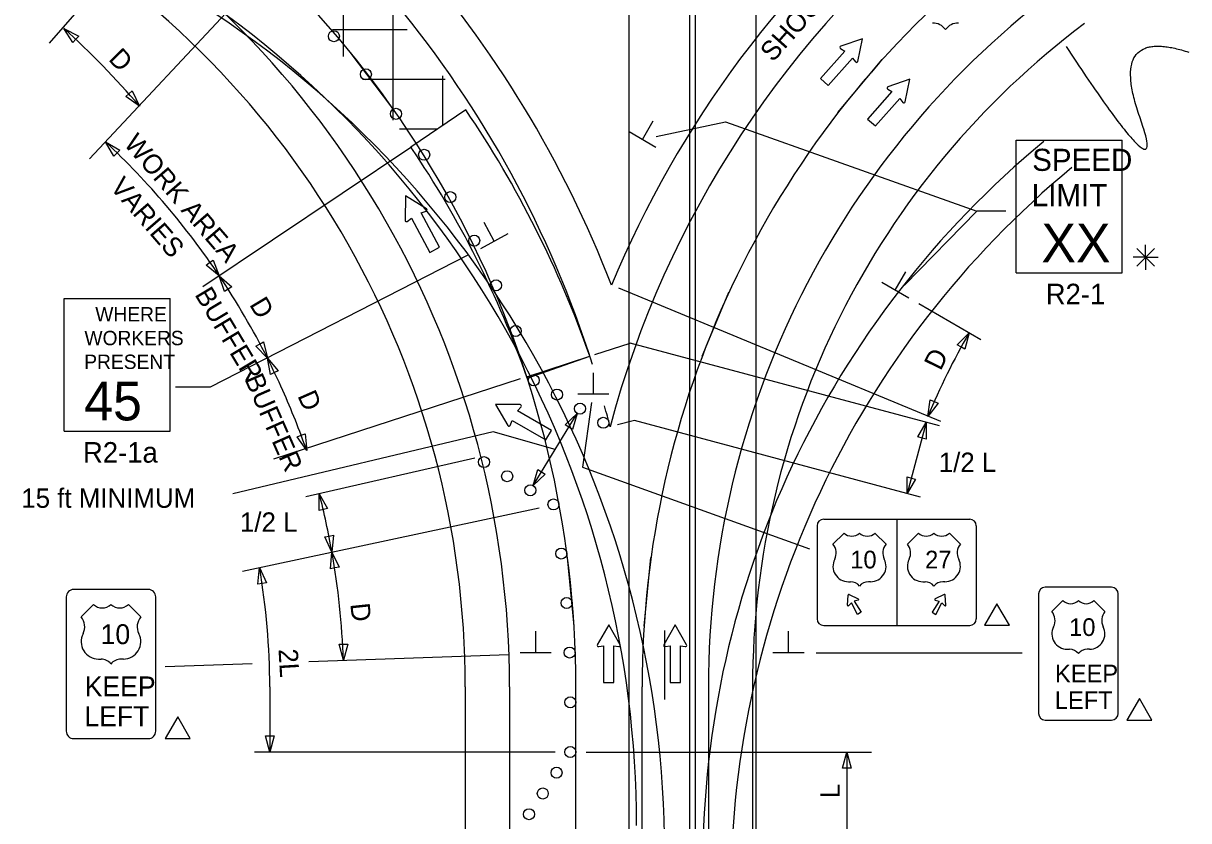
# Model space of a CAD drawing. Extents: x 16284 to 18465, y 5417 to 6974.
# Drawn here: x 16725.1 to 17147, y 6516.3 to 6805 of the extents above; entities that cross this region are included whole.
import ezdxf

# ---------------------------------------------------------------- set-up
doc = ezdxf.new("R2010")
doc.units = 0
for name, color, linetype in [('ALI_LEGAL_EX', 7, 'Continuous'), ('Level 3', 7, 'Continuous'), ('MT_SCRATCH_LEVEL_A', 7, 'Continuous'), ('MT_SCRATCH_LEVEL_E', 7, 'Continuous'), ('PAVT_EDGE_EX', 7, 'Continuous'), ('TRAFFIC_SIGNS_PR', 7, 'Continuous'), ('TYPICAL_EX', 7, 'Continuous'), ('TYPICAL_TEXT_DIMEN_PR', 7, 'Continuous')]:
    doc.layers.add(name, color=color, linetype=linetype)

msp = doc.modelspace()

# ---------------------------------------------------------------- linework, layer by layer
at = {"layer": 'ALI_LEGAL_EX'}
for p, q in [((16944.3, 6974.12), (16944.3, 6155.98)), ((16968.3, 6974.12), (16968.3, 6155.98)), ((16966.29, 6836.53), (16966.29, 5997.6)), ((16990.29, 6836.53), (16990.29, 5997.6)), ((16925.13, 6287.02), (16925.13, 6564.7)), ((16949.13, 6287.02), (16949.13, 6564.7))]:
    msp.add_line(p, q, dxfattribs=at)
for points in [[(16858.51, 6774.55), (16843.42, 6794.48)], [(17020.02, 6772.64), (17036.07, 6791.8)], [(16970.92, 6684.51), (16980.56, 6707.58)], [(16924.57, 6586.71), (16922.17, 6611.6)], [(16949.84, 6586.69), (16952.34, 6611.56)], [(16957.27, 6585.13), (16957.27, 6560.13)]]:
    msp.add_lwpolyline(points, dxfattribs=at)
for centre, radius, start, end in [((16561.13, 6564.7), 364, 0, 53.7921), ((17289.13, 6564.7), 340, 129.5666, 180), ((16583.12, 6514.52), 364, 0, 57.2958), ((16593.27, 6505.1), 364, 0, 57.2958), ((17311.12, 6500.03), 340, 129.5666, 180), ((17321.27, 6490.61), 340, 129.5666, 180)]:
    msp.add_arc(centre, radius, start, end, dxfattribs=at)
at = {"layer": 'Level 3'}
for p, q in [((16954.27, 6763.95), (16979.34, 6769.32)), ((16979.34, 6769.32), (17070.39, 6737)), ((17070.39, 6737), (17044.11, 6710.12)), ((17080.82, 6737), (17070.39, 6737))]:
    msp.add_line(p, q, dxfattribs=at)
at = {"layer": 'MT_SCRATCH_LEVEL_A'}
for p, q in [((16840.96, 6792.95), (16840.96, 6828.84)), ((16858.96, 6769.95), (16858.96, 6808.85)), ((16837.08, 6802.72), (16864.07, 6802.72)), ((16876.96, 6767.98), (16876.96, 6785.97)), ((16847.88, 6784.72), (16877.88, 6784.72)), ((16861.34, 6766.72), (16875.11, 6766.72)), ((16907.37, 6677.02), (16930.2, 6684.43))]:
    msp.add_line(p, q, dxfattribs=at)
at = {"layer": 'MT_SCRATCH_LEVEL_E'}
for p, q in [((17028.96, 6799.34), (17021.08, 6796.66)), ((17027.25, 6791.17), (17028.96, 6799.34)), ((17022.52, 6794.88), (17013.72, 6784.97)), ((17020.99, 6795.82), (17022.52, 6794.88)), ((17016.51, 6782.48), (17025.32, 6792.39)), ((17025.32, 6792.39), (17026.44, 6790.98)), ((17013.72, 6784.97), (17016.51, 6782.48)), ((17038.07, 6781.17), (17039.61, 6780.22)), ((17046.05, 6784.68), (17038.16, 6782)), ((17044.34, 6776.51), (17046.05, 6784.68)), ((17039.61, 6780.22), (17030.8, 6770.31)), ((17033.6, 6767.83), (17042.4, 6777.74)), ((17042.4, 6777.74), (17043.52, 6776.32)), ((17030.8, 6770.31), (17033.6, 6767.83)), ((16937.03, 6587.21), (16932.92, 6579.97)), ((16941.18, 6579.97), (16937.03, 6587.21)), ((16961.09, 6587.21), (16956.98, 6579.97)), ((16965.24, 6579.97), (16961.09, 6587.21)), ((16933.41, 6579.29), (16935.18, 6579.6)), ((16935.18, 6579.6), (16935.18, 6566.35)), ((16938.92, 6566.35), (16938.92, 6579.6)), ((16938.92, 6579.6), (16940.7, 6579.29)), ((16957.46, 6579.29), (16959.24, 6579.6)), ((16959.24, 6579.6), (16959.24, 6566.35)), ((16962.98, 6566.35), (16962.98, 6579.6)), ((16962.98, 6579.6), (16964.76, 6579.29)), ((16935.18, 6566.35), (16938.92, 6566.35)), ((16959.24, 6566.35), (16962.98, 6566.35))]:
    msp.add_line(p, q, dxfattribs=at)
for centre, start, end in [((17021.24, 6796.22), 108.8028, 238.3418), ((17026.8, 6791.28), 218.4141, 348.1511), ((17038.32, 6781.56), 108.8028, 238.3418), ((17043.88, 6776.62), 218.4141, 348.1511), ((16933.33, 6579.75), 150.4248, 279.9638), ((16940.77, 6579.75), 260.0362, 29.7731), ((16957.39, 6579.75), 150.4248, 279.9638), ((16964.83, 6579.75), 260.0362, 29.7731)]:
    msp.add_arc(centre, 0.463, start, end, dxfattribs=at)
at = {"layer": 'PAVT_EDGE_EX'}
for p, q in [((16885.31, 6773.63), (16865.43, 6760.16)), ((16907.55, 6676.49), (16930.2, 6684.43)), ((16885.13, 6564.7), (16885.13, 6289.11)), ((16901.13, 6564.7), (16901.13, 6289.11)), ((16973.13, 6564.7), (16973.13, 6289.11)), ((16989.13, 6564.7), (16989.13, 6289.11))]:
    msp.add_line(p, q, dxfattribs=at)
for centre, radius, start, end in [((16561.13, 6564.7), 404, 21.0961, 61.7914), ((16561.13, 6564.7), 388, 17.512, 61.7914), ((16561.13, 6564.7), 340, 0, 59.3712), ((17289.13, 6564.7), 380, 128.9165, 157.5011), ((17289.13, 6564.7), 364, 128.3887, 165.0045), ((16561.13, 6564.7), 324, 0, 59.2832), ((17289.13, 6564.7), 316, 126.5777, 180), ((17289.13, 6564.7), 300, 126.8181, 180), ((16564.05, 6556.06), 388, 19.3199, 34.1071), ((16564.05, 6556.06), 363.99, 19.32, 34.1071), ((16561.13, 6564.7), 388, 14.0482, 15.2048), ((17289.13, 6564.7), 300, 180, 180.00000277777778)]:
    msp.add_arc(centre, radius, start, end, dxfattribs=at)
at = {"layer": 'TRAFFIC_SIGNS_PR'}
for p, q in [((17084.6, 6762.67), (17123, 6762.67)), ((17084.6, 6714.67), (17084.6, 6762.67)), ((17123, 6714.67), (17123, 6762.67)), ((17084.6, 6714.67), (17123, 6714.67)), ((16739.84, 6705.34), (16778.24, 6705.34)), ((16739.84, 6657.34), (16739.84, 6705.34)), ((16778.24, 6657.34), (16778.24, 6705.34)), ((16739.84, 6657.34), (16778.24, 6657.34)), ((17014.89, 6625.42), (17067.75, 6625.42)), ((17041.32, 6625.42), (17041.32, 6586.97)), ((17012.48, 6623.02), (17012.48, 6589.37)), ((17070.15, 6623.02), (17070.15, 6589.37)), ((16770.33, 6599.99), (16743.33, 6599.99)), ((17119.12, 6600.78), (17095.08, 6600.78)), ((16740.63, 6597.29), (16740.63, 6548.69)), ((16773.03, 6548.69), (16773.03, 6597.29)), ((17023.47, 6594.33), (17023.76, 6597.96)), ((17024.13, 6598.17), (17027.41, 6596.6)), ((17058.5, 6598.17), (17055.22, 6596.6)), ((17059.16, 6594.33), (17058.88, 6597.96)), ((17092.68, 6598.37), (17092.68, 6555.12)), ((17121.52, 6555.12), (17121.52, 6598.37)), ((17014.89, 6586.97), (17067.75, 6586.97)), ((17095.08, 6552.72), (17119.12, 6552.72)), ((16743.33, 6545.99), (16770.33, 6545.99))]:
    msp.add_line(p, q, dxfattribs=at)
for points in [[(17027.37, 6596.12), (17025.96, 6595.73), (17028.48, 6591.74), (17027.15, 6590.98), (17024.96, 6595.15), (17023.92, 6594.12)], [(17055.26, 6596.12), (17056.67, 6595.73), (17054.15, 6591.74), (17055.49, 6590.98), (17057.68, 6595.15), (17058.72, 6594.12)]]:
    msp.add_lwpolyline(points, dxfattribs=at)
for centre in [(16837.54, 6800.28), (16849.13, 6786.51), (16860.04, 6772.19), (16870.23, 6757.36), (16879.67, 6742.03), (16888.35, 6726.27), (16896.25, 6710.09), (16903.34, 6693.55), (16909.91, 6675.67), (16918.3, 6670.56), (16926.68, 6665.45), (16935.07, 6660.34), (16891.89, 6646.1), (16900.27, 6640.99), (16908.66, 6635.88), (16917.04, 6630.77), (16917.04, 6630.77), (16919.88, 6612.99), (16921.84, 6595.1), (16922.9, 6577.14), (16923.12, 6559.14), (16923.12, 6541.14), (16923.12, 6541.14), (16918.15, 6533.63), (16913.18, 6526.12), (16908.21, 6518.62)]:
    msp.add_circle(centre, 2, dxfattribs=at)
for centre, radius, start, end in [((17014.88, 6623.02), 2.4, 90, 180), ((17014.88, 6623.02), 2.4, 90, 180), ((17067.75, 6623.02), 2.4, 0, 90), ((16743.33, 6597.29), 2.7, 90, 180), ((16770.33, 6597.29), 2.7, 0, 90), ((17095.09, 6598.37), 2.4, 90, 180), ((17119.12, 6598.37), 2.4, 0, 90), ((17024.02, 6597.94), 0.261, 64.4823, 175.5177), ((17027.3, 6596.37), 0.261, 285.9885, 64.4823), ((17055.34, 6596.37), 0.261, 115.5177, 254.0115), ((17058.62, 6597.94), 0.261, 4.4823, 115.5177), ((17023.73, 6594.31), 0.261, 175.5177, 314.0115), ((17058.9, 6594.31), 0.261, 225.9885, 4.4823), ((17014.88, 6589.37), 2.4, 180, 270), ((17067.75, 6589.37), 2.4, 270, 0), ((17095.09, 6555.12), 2.4, 180, 270), ((17119.12, 6555.12), 2.4, 270, 0), ((16743.33, 6548.69), 2.7, 180, 270), ((16770.33, 6548.69), 2.7, 270, 0)]:
    msp.add_arc(centre, radius, start, end, dxfattribs=at)
at = {"layer": 'TYPICAL_EX'}
for p, q in [((17018.24, 6616.41), (17022.24, 6620.41)), ((17037.46, 6616.41), (17033.46, 6620.41)), ((17045.17, 6616.41), (17049.18, 6620.41)), ((17064.4, 6616.41), (17060.39, 6620.41)), ((17023.84, 6602.78), (17024.64, 6602.78)), ((17031.86, 6602.78), (17031.06, 6602.78)), ((17050.77, 6602.78), (17051.57, 6602.78)), ((17058.8, 6602.78), (17057.99, 6602.78)), ((17097.49, 6591.97), (17101.49, 6595.97)), ((17116.71, 6591.97), (17112.71, 6595.97)), ((16746.03, 6590.09), (16750.53, 6594.59)), ((16767.63, 6590.09), (16763.13, 6594.59)), ((17103.09, 6578.34), (17103.89, 6578.34)), ((17111.11, 6578.34), (17110.31, 6578.34)), ((16752.32, 6574.78), (16753.22, 6574.78)), ((16761.33, 6574.78), (16760.44, 6574.78))]:
    msp.add_line(p, q, dxfattribs=at)
for centre, radius, start, end in [((17054.27, 6799.16), 5.91, 37.1038, 90.1385), ((17063.69, 6799.16), 5.91, 89.8615, 142.8962), ((17014.44, 6613.2), 4.97, 333.0977, 40.1936), ((17025.05, 6623.33), 4.05, 226.1404, 313.8596), ((17030.66, 6623.33), 4.05, 226.1404, 313.8596), ((17041.26, 6613.2), 4.97, 139.8064, 206.9023), ((17041.38, 6613.2), 4.97, 333.0977, 40.1936), ((17051.98, 6623.33), 4.05, 226.1404, 313.8596), ((17057.59, 6623.33), 4.05, 226.1404, 313.8596), ((17068.19, 6613.2), 4.97, 139.8064, 206.9023), ((17023.85, 6608.38), 5.6, 152.6698, 269.9013), ((17031.85, 6608.38), 5.6, 270.0987, 27.3302), ((17050.78, 6608.38), 5.6, 152.6698, 269.9013), ((17058.78, 6608.38), 5.6, 270.0987, 27.3302), ((17024.65, 6598.77), 4.01, 37.1038, 90.1385), ((17031.05, 6598.77), 4.01, 89.8615, 142.8962), ((17051.58, 6598.77), 4.01, 37.1038, 90.1385), ((17057.98, 6598.77), 4.01, 89.8615, 142.8962), ((17104.3, 6598.89), 4.05, 226.1404, 313.8596), ((17109.9, 6598.89), 4.05, 226.1404, 313.8596), ((16753.68, 6597.86), 4.55, 226.1404, 313.8596), ((16759.98, 6597.86), 4.55, 226.1404, 313.8596), ((17093.69, 6588.76), 4.97, 333.0977, 40.1936), ((17120.51, 6588.76), 4.97, 139.8064, 206.9023), ((16741.76, 6586.48), 5.58, 333.0977, 40.1936), ((16771.89, 6586.48), 5.58, 139.8064, 206.9023), ((16752.33, 6581.07), 6.29, 152.6698, 269.9013), ((16761.32, 6581.07), 6.29, 270.0987, 27.3302), ((17103.1, 6583.94), 5.6, 152.6698, 269.9013), ((17111.1, 6583.94), 5.6, 270.0987, 27.3302), ((17103.9, 6574.33), 4.01, 37.1038, 90.1385), ((17110.3, 6574.33), 4.01, 89.8615, 142.8962), ((16753.23, 6570.27), 4.51, 37.1038, 90.1385), ((16760.42, 6570.27), 4.51, 89.8615, 142.8962)]:
    msp.add_arc(centre, radius, start, end, dxfattribs=at)
at = {"layer": 'TYPICAL_TEXT_DIMEN_PR'}
for p, q in [((16828.63, 6840.91), (16749.09, 6755.95)), ((16734.61, 6797.73), (16746.22, 6811.22)), ((16743.04, 6798.03), (16739.73, 6803.11)), ((16739.73, 6803.11), (16745.14, 6800.36)), ((16744.09, 6799.2), (16743.04, 6798.03)), ((16745.14, 6800.36), (16744.09, 6799.2)), ((16762.15, 6778.44), (16763.34, 6779.46)), ((16767.15, 6775), (16762.15, 6778.44)), ((16763.34, 6779.46), (16764.54, 6780.48)), ((16764.54, 6780.48), (16767.15, 6775)), ((16949.29, 6762.86), (16953.18, 6769.6)), ((16954.16, 6760.04), (16944.42, 6765.67)), ((16757.88, 6756.82), (16754.82, 6762.07)), ((16754.82, 6762.07), (16760.09, 6759.05)), ((16865.73, 6760.25), (16790.09, 6709.61)), ((16758.98, 6757.94), (16757.88, 6756.82)), ((16760.09, 6759.05), (16758.98, 6757.94)), ((16863.48, 6742.52), (16863.29, 6733.64)), ((16871.04, 6737.82), (16863.48, 6742.52)), ((16864.09, 6733.24), (16865.6, 6734.44)), ((16865.6, 6734.44), (16872.31, 6721.99)), ((16869.11, 6736.33), (16870.94, 6736.94)), ((16875.82, 6723.89), (16869.11, 6736.33)), ((16895.61, 6726.03), (16891.9, 6732.88)), ((16900.55, 6728.71), (16890.66, 6723.36)), ((16872.31, 6721.99), (16875.82, 6723.89)), ((17134.65, 6723.44), (17128.27, 6717.07)), ((17128.28, 6723.44), (17134.65, 6717.07)), ((17131.46, 6720.26), (17131.46, 6724.71)), ((16791.28, 6717.38), (16792.54, 6718.31)), ((16792.54, 6718.31), (16793.81, 6719.24)), ((16886.08, 6720.97), (16792.73, 6673.17)), ((16793.81, 6719.24), (16796.02, 6713.59)), ((17131.46, 6720.26), (17126.93, 6720.26)), ((17131.46, 6720.26), (17134.65, 6720.26)), ((17131.46, 6720.26), (17135.94, 6720.26)), ((17131.46, 6720.26), (17131.46, 6715.76)), ((16796.02, 6713.59), (16791.28, 6717.38)), ((16797.92, 6707.82), (16796.03, 6713.59)), ((16796.03, 6713.59), (16800.55, 6709.55)), ((17040.79, 6708.3), (17044.68, 6715.04)), ((16800.55, 6709.55), (16799.24, 6708.68)), ((17045.66, 6705.49), (17035.92, 6711.11)), ((16799.24, 6708.68), (16797.92, 6707.82)), ((17057.24, 6660.74), (16940.65, 6709.03)), ((17071.84, 6690.34), (17049.33, 6703.35)), ((17063.22, 6688.55), (17067.51, 6692.84)), ((17067.51, 6692.84), (17065.94, 6686.98)), ((16809.25, 6688.09), (16810.63, 6688.85)), ((16813.47, 6683.73), (16809.25, 6688.09)), ((16810.63, 6688.85), (16812, 6689.61)), ((16812, 6689.61), (16813.47, 6683.73)), ((16932.03, 6685.02), (16944.83, 6689.18)), ((17056.82, 6659.18), (16944.83, 6689.18)), ((17064.58, 6687.77), (17063.22, 6688.55)), ((16814.59, 6677.82), (16813.45, 6683.78)), ((16813.45, 6683.78), (16817.42, 6679.19)), ((17065.94, 6686.98), (17064.58, 6687.77)), ((16816.01, 6678.5), (16814.59, 6677.82)), ((16815.83, 6647.32), (16905.16, 6676.31)), ((16817.42, 6679.19), (16816.01, 6678.5)), ((16931.49, 6670.66), (16931.49, 6678.45)), ((16792.73, 6673.17), (16780.17, 6673.19)), ((16904.93, 6666.94), (16896.03, 6666.98)), ((16896.03, 6666.98), (16900.52, 6659.32)), ((16937.12, 6670.66), (16925.87, 6670.66)), ((16930.86, 6667.69), (16927.57, 6644.26)), ((17052.62, 6662.66), (17053.41, 6668.67)), ((17056.31, 6667.47), (17052.62, 6662.66)), ((17053.41, 6668.67), (17054.86, 6668.07)), ((17054.86, 6668.07), (17056.31, 6667.47)), ((16904.06, 6664.66), (16905.3, 6666.13)), ((16916.3, 6657.58), (16904.06, 6664.66)), ((16909.7, 6637.59), (16925.64, 6663.74)), ((16921.25, 6659.55), (16925.64, 6663.74)), ((16925.64, 6663.74), (16923.93, 6657.92)), ((16926.68, 6665.45), (16926.68, 6665.45)), ((16901.4, 6659.4), (16902.06, 6661.21)), ((16902.06, 6661.21), (16914.3, 6654.12)), ((16922.59, 6658.74), (16921.25, 6659.55)), ((16923.93, 6657.92), (16922.59, 6658.74)), ((16933.36, 6661.39), (16933.36, 6661.38)), ((16946.44, 6661.11), (16940.28, 6659.57)), ((17049.91, 6633.39), (16946.44, 6661.11)), ((17052.03, 6660.46), (17045.12, 6634.68)), ((17048.99, 6655.21), (17052.03, 6660.46)), ((17052.03, 6660.46), (17052.03, 6654.39)), ((16895.24, 6657.1), (16800.9, 6634.63)), ((16824.21, 6655.27), (16825.69, 6655.81)), ((16827.69, 6650.3), (16824.21, 6655.27)), ((16825.69, 6655.81), (16827.16, 6656.35)), ((16827.16, 6656.35), (16827.69, 6650.3)), ((16917.67, 6650.66), (16895.24, 6657.1)), ((16914.3, 6654.12), (16916.3, 6657.58)), ((17050.51, 6654.8), (17048.99, 6655.21)), ((17052.03, 6654.39), (17050.51, 6654.8)), ((16888.59, 6647.57), (16827.38, 6633.51)), ((16909.7, 6637.59), (16911.41, 6643.41)), ((16914.09, 6641.77), (16909.7, 6637.59)), ((16911.41, 6643.41), (16912.75, 6642.59)), ((16912.75, 6642.59), (16914.09, 6641.77)), ((16927.57, 6644.26), (17009.73, 6614.66)), ((17045.12, 6634.68), (17045.12, 6640.75)), ((17045.12, 6640.75), (17046.64, 6640.34)), ((17048.15, 6639.93), (17045.12, 6634.68)), ((17046.64, 6640.34), (17048.15, 6639.93)), ((16832.2, 6628.56), (16832.26, 6634.63)), ((16832.26, 6634.63), (16835.24, 6629.34)), ((16804.43, 6606.62), (16911.9, 6629.56)), ((16833.72, 6628.95), (16832.2, 6628.56)), ((16835.24, 6629.34), (16833.72, 6628.95)), ((16834.27, 6619.04), (16835.82, 6619.31)), ((16836.84, 6613.54), (16834.27, 6619.04)), ((16835.82, 6619.31), (16837.36, 6619.59)), ((16837.36, 6619.59), (16836.84, 6613.54)), ((16836.31, 6607.49), (16836.84, 6613.54)), ((16836.84, 6613.54), (16839.41, 6608.04)), ((16810.06, 6601.89), (16810.59, 6607.94)), ((16810.59, 6607.94), (16813.16, 6602.44)), ((16839.41, 6608.04), (16837.86, 6607.77)), ((16837.86, 6607.77), (16836.31, 6607.49)), ((16811.61, 6602.16), (16810.06, 6601.89)), ((16813.16, 6602.44), (16811.61, 6602.16)), ((16910.61, 6577.09), (16910.61, 6584.88)), ((17002.15, 6577.09), (17002.15, 6584.88)), ((16840.97, 6574.34), (16839.4, 6580.2)), ((16839.4, 6580.2), (16840.97, 6580.2)), ((16840.97, 6580.2), (16842.54, 6580.2)), ((16842.54, 6580.2), (16840.97, 6574.34)), ((16828.48, 6573.91), (16900.93, 6576.4)), ((16916.24, 6577.09), (16904.99, 6577.09)), ((17007.77, 6577.09), (16996.52, 6577.09)), ((17012.13, 6577.09), (17086.74, 6577.09)), ((16776.49, 6572.12), (16807.93, 6573.2)), ((16814.31, 6564.7), (16814.31, 6541.14)), ((16814.31, 6541.14), (16812.74, 6547)), ((16812.74, 6547), (16814.31, 6547)), ((16814.31, 6547), (16815.88, 6547)), ((16815.88, 6547), (16814.31, 6541.14)), ((16917.63, 6541.14), (16808.77, 6541.14)), ((16928.89, 6541.14), (17032.15, 6541.14)), ((17021.67, 6535.28), (17023.24, 6541.14)), ((17023.24, 6541.14), (17023.24, 6509.03)), ((17023.24, 6541.14), (17024.81, 6535.28)), ((17023.24, 6535.28), (17021.67, 6535.28)), ((17024.81, 6535.28), (17023.24, 6535.28))]:
    msp.add_line(p, q, dxfattribs=at)
for points in [[(17077.63, 6594.84), (17073.1, 6587.01), (17082.15, 6587.01)], [(17129.19, 6560.48), (17124.66, 6552.65), (17133.71, 6552.65)], [(16780.99, 6553.82), (16776.46, 6545.99), (16785.51, 6545.99)]]:
    msp.add_lwpolyline(points, close=True, dxfattribs=at)
for centre, radius, start, end in [((16540.99, 6581.76), 297.48, 40.5126, 48.082), ((16563.46, 6557.67), 280, 33.8403, 46.8862), ((16870.77, 6737.4), 0.494, 288.3781, 58.115), ((16863.79, 6733.64), 0.494, 178.7668, 308.3057), ((16563.46, 6557.67), 280, 26.7575, 33.8392), ((17289.13, 6564.7), 256, 149.9625, 157.5013), ((16563.46, 6557.67), 280, 24.1124, 26.7689), ((16563.46, 6557.67), 280, 19.32, 24.1124), ((16904.92, 6666.44), 0.494, 319.9691, 89.7061), ((16900.94, 6659.57), 0.494, 210.3578, 339.8967), ((16561.13, 6564.7), 280, 10.0461, 14.4629), ((16561.13, 6564.7), 280, 1.9734, 10.046), ((16561.13, 6564.7), 253.18, 0, 9.834)]:
    msp.add_arc(centre, radius, start, end, dxfattribs=at)
msp.add_open_spline([(17102.66, 6796.57), (17140.9, 6738.4), (17117.68, 6804.1), (17147.04, 6794.52)], degree=2, dxfattribs=at)

# ---------------------------------------------------------------- texts
at = {"layer": 'TRAFFIC_SIGNS_PR'}
for s, height, p in [('SPEED', 8, (17090.37, 6751.53)), ('LIMIT', 8, (17090.21, 6738.73)), ('XX', 14.031, (17093.72, 6718.43)), ('R2-1', 7.44, (17095.28, 6703.23)), ('WHERE', 5.2, (16751.15, 6697.02)), ('WORKERS', 5.2, (16747.22, 6688.42)), ('PRESENT', 5.2, (16747.15, 6679.82)), ('45', 14.031, (16747.14, 6661.19)), ('R2-1a', 7.44, (16746.69, 6645.9)), ('10', 6.408, (17024.51, 6607.6)), ('27', 6.408, (17051.61, 6607.6)), ('10', 7.2, (16753.07, 6580.19)), ('10', 6.408, (17103.76, 6583.15)), ('KEEP', 6.408, (17098.63, 6566.33)), ('KEEP', 7.2, (16747.31, 6561.29)), ('LEFT', 6.408, (17098.54, 6556.72)), ('LEFT', 7.2, (16747.21, 6550.49))]:
    msp.add_text(s, height=height, dxfattribs=at).set_placement(p)
at = {"layer": 'TYPICAL_TEXT_DIMEN_PR'}
for s, rotation, p in [('SHOULDER', 48.378, (16996.49, 6790.64)), ('D', 314.2974, (16755.59, 6791.75)), ('WORK AREA', 310.7541, (16761.18, 6761.17)), ('VARIES', 310.7541, (16756.21, 6745.48)), ('BUFFER', 300.9582, (16786.97, 6706.78)), ('D', 300.9582, (16806.76, 6703.15)), ('D', 63.7334, (17057.2, 6678.9)), ('BUFFER', 293.7043, (16805.06, 6676.23)), ('D', 293.7043, (16824.24, 6670.13)), ('D', 276.0098, (16843.47, 6594.75)), ('2L', 273.4242, (16817.47, 6578.34)), ('L', 90, (17020.68, 6524.44))]:
    msp.add_text(s, height=7, rotation=rotation, dxfattribs=at).set_placement(p)
for s, p in [('1/2 L', (17056.56, 6642.53)), ('15 ft MINIMUM', (16724.37, 6629.55)), ('1/2 L', (16803.53, 6620.89))]:
    msp.add_text(s, height=7, dxfattribs=at).set_placement(p)

doc.saveas('drawing.dxf')
